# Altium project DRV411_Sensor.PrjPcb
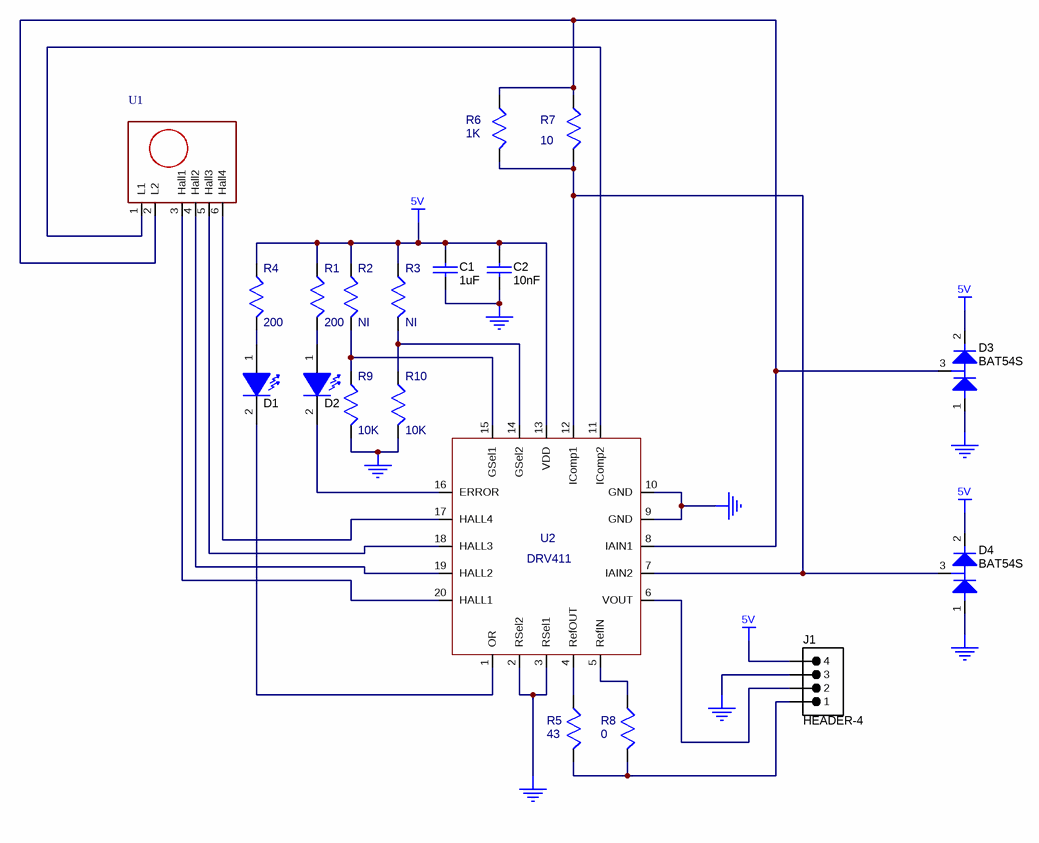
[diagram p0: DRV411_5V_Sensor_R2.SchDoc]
CopyrightYear: 2014; PCB_Layout: Tom Hendrick; PCB_Rev: 2; PRJ_Customer: Public Release; PRJ_Engineer: Tom Hendrick; PRJ_Number: 180; PRJ_Title: TI Designs Precision; SCH_Rev: 2; TechSupport: http://www.ti.com/support
1 sheet, 19 parts. Net scope: global (net labels, ports and power ports of the same name join across sheets).
Board file: DRV411_5V_Sensor_R2.PcbDoc

## Sheet DRV411_5V_Sensor_R2.SchDoc: Schematic for Lit # TIDU674
size Letter; SheetNumber: 1; SheetTotal: 1; DrawnBy: Tom Hendrick; PageSetup: Record=PageOptions|CenterHorizontal=True|CenterVertical=True|PrintScale=0.94|XCorrection=1.00|YCorrection=1.00|PrintKind=0|BorderSize=5000000|LeftOffset=0|BottomOffset=0|Orientation=2|PaperLength=1000|PaperWidth=1000|Scale=100|PaperSource=15|PrintQuality=600|MediaType=1|DitherType=10|PaperKind=Letter|PrintScaleMode=1

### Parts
C1  1uF  [0603]
C2  10nF  [0603]
D1  LTST-C170KSKT  [LED_LTST-C170]  (value not drawn)
D2  LTST-C170KSKT  [LED_LTST-C170]  (value not drawn)
D3  BAT54S  [SOT23]
D4  BAT54S  [SOT23]
J1  HEADER-4  [HDR1X4]
R1  200  [0603]
R2  NI  [0603]
R3  NI  [0603]
R4  200  [0603]
R5  43  [0603]
R6  1K  [0603]
R7  10  [1206]
R8  0  [0603]
R9  10K  [0603]
R10  10K  [0603]
U1  *  [TQPL_Passive]  (value not drawn)
U2  DRV411  [QFN-20 (RTJ)]

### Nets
5V: C1.1 C2.1 D3.2 D4.2 J1.4 R1.1 R2.1 R3.1 R4.1 U2.13(VDD)
GND: C1.2 C2.2 D3.1 D4.1 J1.3 R9.1 R10.1 U2.2(RSel2) U2.3(RSel1) U2.9(GND) U2.10(GND)
NetD1_1: D1.1(A) R4.2
NetD1_2: D1.2(K) U2.1(OR)
NetD2_1: D2.1(A) R1.2
NetD2_2: D2.2(K) U2.16(ERROR)
NetD3_3: D3.3 R6.1 R7.1 U1.2(L2) U2.8(IAIN1)
NetD4_3: D4.3 R6.2 R7.2 U2.7(IAIN2) U2.12(IComp1)
NetJ1_1: J1.1 R5.2 R8.2
NetJ1_2: J1.2 U2.6(VOUT)
NetR2_2: R2.2 R9.2 U2.15(GSel1)
NetR3_2: R3.2 R10.2 U2.14(GSel2)
NetR5_1: R5.1 U2.4(RefOUT)
NetR8_1: R8.1 U2.5(RefIN)
NetU1_1: U1.1(L1) U2.11(IComp2)
NetU1_3: U1.3(Hall1) U2.20(HALL1)
NetU1_4: U1.4(Hall2) U2.19(HALL2)
NetU1_5: U1.5(Hall3) U2.18(HALL3)
NetU1_6: U1.6(Hall4) U2.17(HALL4)

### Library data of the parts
C1 C2 = CAP_603: Multilayer Ceramic - 0603Size
D1 D2 = LTST-C170KSKT: LED, Yellow , SMD; Manufacturer: Lite-On; Type: AlInGaP; Vf_V: 2; Value2: 2V; Io_A: 0.02; Value1: W; U/M: EA
D3 D4 = DUALDIODE: Dual Schotkey
J1 = HEADER-4: 4x1 100 mil male header
R1-R6 R8-R10 = RES_603: Resister - 0603Size
R7 = RES_1206: Resister - 1206Size
U1 = TQPL_PASSIVE: TopStek Passive Hall Sensor

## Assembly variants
001: not fitted FID1 FID2 FID3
